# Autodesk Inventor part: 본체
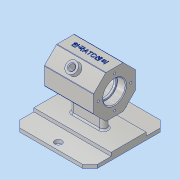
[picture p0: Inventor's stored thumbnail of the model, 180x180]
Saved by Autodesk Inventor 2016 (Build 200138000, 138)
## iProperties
Created: 2018-06
Part Number: 본체
Material: 알루미늄 6061
Document SubType Name: Modeling
Designer: 605-17
Density: 2.7 g/cm^3
Appearance: 알루미늄 - 평지
Mass: 552.439 g
Surface Area: 602.386 cm^2
Volume: 204.607 cm^3
Author: 605-17
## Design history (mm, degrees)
sketch "스케치1"
  geometry: L1 (-45, 55)-(45, 55); L2 (55, 45)-(55, -45); L3 (45, -55)-(-45, -55); L4 (-55, -45)-(-55, 45); L5 (-45, 55)-(-55, 45); L6 (45, 55)-(55, 45); L7 (-45, -55)-(-55, -45); L8 (45, -55)-(55, -45); 7 further points
  constraints: 16 end point, 8 point on line, 2 midpoint, 2 parallel, 2 perpendicular, 1 horizontal, 1 horizontal alignment, 1 vertical alignment
  dimensions: "d0" = 110 distance of point (-55, 55) point (55, 55); "d1" = 10 distance of L1.start point (-55, 55); "d2" = 10 distance of L4.end point (-55, 55) (= d1); "d3" = 10 distance of L1.end point (55, 55) (= d1); "d4" = 10 distance of L2.start point (55, 55) (= d3); "d5" = 10 distance of L3.end point (-55, -55) (= d1); "d6" = 10 distance of L4.start point (-55, -55) (= d5); "d7" = 10 distance of L3.start point (55, -55) (= d1); "d8" = 10 distance of L2.end point (55, -55) (= d7)
extrude "돌출1" new body sketch "스케치1" distance "d9" = 5; taper "d10" = 0 deg
sketch "스케치2"
  geometry: L1 (-55, 45)-(-55, -45) reference; L2 (-45, -55)-(45, -55) reference; L3 (55, -45)-(55, 45) reference; L4 (45, 55)-(-45, 55) reference; L5 (-55, 45)-(-55, -45) reference; L6 (55, -45)-(55, 45) reference; L7 (-55, 25)-(55, 25); L8 (-55, -25)-(55, -25); L9 (55, -25)-(55, 25); L10 (-55, 25)-(-55, -25); 1 further point
  constraints: 8 end point, 4 point on line, 2 collinear, 2 perpendicular
  dimensions: "d11" = 30 distance between parallel lines of L7 L4; "d12" = 30 distance between parallel lines of L2 L8
extrude "돌출2" join sketch "스케치2" distance "d13" = 5; taper "d14" = 0 deg
sketch "스케치3" dims "d15" = 60
  geometry: L1 (25, 10)-(-25, 10) reference; L2 (-30, 74.426)-(-12.426, 92); L3 (-12.426, 92)-(12.426, 92); L4 (12.426, 92)-(30, 74.426); L5 (30, 74.426)-(30, 49.574); L6 (30, 49.574)-(12.426, 32); L7 (12.426, 32)-(-12.426, 32); L8 (-12.426, 32)-(-30, 49.574); L9 (-30, 49.574)-(-30, 74.426); 4 further points
  constraints: 16 end point, 1 coincident, 1 horizontal alignment, 1 midpoint, 1 vertical alignment, 19 other
  dimensions: "d16" = 62 distance of point (0, 0) point (0, 62); "d17" = 92 distance from line of point (0, 0) L3
extrude "돌출3" join sketch "스케치3" stored distance "d18" = 70; taper "d19" = 0 deg
sketch "스케치4"
  geometry: L1 (-19, 5)-(19, 5); L2 (19, -5)-(-19, -5); A1 r 5 centre (19, 0) between (19, -5) and (19, 5); A2 r 5 centre (-19, 0) between (-19, 5) and (-19, -5); 2 further points
  constraints: 4 end point, 4 point on circle, 4 tangent, 2 centre point, 2 horizontal, 1 horizontal alignment, 1 midpoint, 1 vertical alignment
  dimensions: "d20" = 5 radius of A2; "d21" = 38 distance of A1.centre A2.centre
extrude "돌출4" join sketch "스케치4" distance "d22" = 50; taper "d23" = 0 deg
sketch "스케치5"
  geometry: L1 (35, 92)-(35, 74.426) reference; L2 (35, 74.426)-(35, 49.574) reference; L3 (35, 49.574)-(35, 32) reference; L4 (-35, 74.426)-(-35, 92) reference; L5 (-35, 49.574)-(-35, 74.426) reference; L6 (-35, 32)-(-35, 49.574) reference; L7 (35, 62)-(-35, 62); L8 (35, 78)-(23, 78); L9 (23, 78)-(23, 76); L10 (23, 76)-(20, 76); L11 (20, 76)-(20, 87); L12 (20, 87)-(-20, 87); L13 (-20, 87)-(-20, 76); L14 (-20, 76)-(-23, 76); L15 (-23, 76)-(-23, 78); L16 (-23, 78)-(-35, 78); L17 (-35, 78)-(-35, 62); L18 (35, 78)-(35, 62); 1 further point
  constraints: 24 end point, 6 perpendicular, 5 collinear, 5 point on line, 2 midpoint, 1 vertical
  dimensions: "d24" = 32 diameter of L8 L7; "d25" = 28 diameter of L10 L7; "d26" = 50 diameter of L12 L7; "d27" = 12 distance between parallel lines of L1 L9; "d28" = 40 distance between parallel lines of L13 L11
revolve "회전1" sketch "스케치5" stored, may be unused: angle "d29" = 90 deg
sketch "스케치6"
  geometry: C1 r 16 at (-62, 0) reference; 2 further points
  constraints: 1 horizontal alignment
  dimensions: "d30" = 23 distance of C1.centre point (-85, 0)
hole "구멍1" sketch "스케치6" at (-85, 0) diameter "d31" = 3.242; stored, may be unused: countersink angle "d35" = 90 deg, drill point angle "d37" = 118 deg; dims "d32" = 8, "d33" = 4, "d34" = 2, "d36" = 10
sketch "스케치7"
  geometry: L1 (45, 55)-(-45, 55) reference; L2 (-45, -55)-(45, -55) reference; C1 r 5 at (0, 45); C2 r 5 at (0, -45); 1 further point
  constraints: 2 centre point, 2 vertical alignment, 1 equal radius
  dimensions: "d41" = 10 distance from line of L2 C2.centre; "d42" = 10 distance from line of L1 C1.centre; "d43" = 10 diameter of C1
extrude "돌출5" cut sketch "스케치7" distance "d44" = 50; taper "d45" = 0 deg
sketch "스케치8"
  geometry: L1 (0, 0)-(0, 24.853) reference; C1 r 8 at (35, 12.426); 2 further points
  constraints: 1 centre point, 1 horizontal alignment, 1 midpoint, 1 vertical alignment
  dimensions: "d46" = 16 diameter of C1
extrude "돌출6" join sketch "스케치8" distance "d47" = 7; taper "d48" = 0 deg
sketch "스케치9"
  geometry: L1 (70, 42.426)-(0, 42.426) reference; L2 (0, 24.853)-(0, 42.426) reference; 2 further points
  constraints: 1 other
  dimensions: "d49" = 30 distance from line of point (35, 12.426) L1; "d50" = 35 distance from line of point (35, 12.426) L2
feature "엠보싱1" sketch "스케치9" dims "d0" = 110, "d1" = 10, "d2" = 10 (= d1), "d3" = 10 (= d1), "d4" = 10 (= d3), "d5" = 10 (= d1), "d6" = 10 (= d5), "d7" = 10 (= d1), "d8" = 10 (= d7), "d51" = 0.5, "d52" = 0
hole "구멍2" diameter "d55" = 8; stored, may be unused: countersink angle "d59" = 90 deg, drill point angle "d61" = 0 deg; dims "d56" = 8, "d57" = 4, "d58" = 2, "d60" = 20, "d71" = 10, "d72" = 10
chamfer "모따기1" distance "d62" = 1; stored, may be unused: second distance "d63" = 2, angle "d64" = 45 deg
fillet "모깎기1" dims "d65" = 1
fillet "모깎기2" dims "d66" = 0.3
fillet "모깎기3" dims "d67" = 2
fillet "모깎기4" dims "d68" = 3
chamfer "모따기2" distance "d69" = 1; stored, may be unused: second distance "d70" = 2, angle "d73" = 45 deg
node "솔리드1"
pattern_circular "원형 패턴1" dims angle "d39" = 360 deg
mirror "대칭1"
